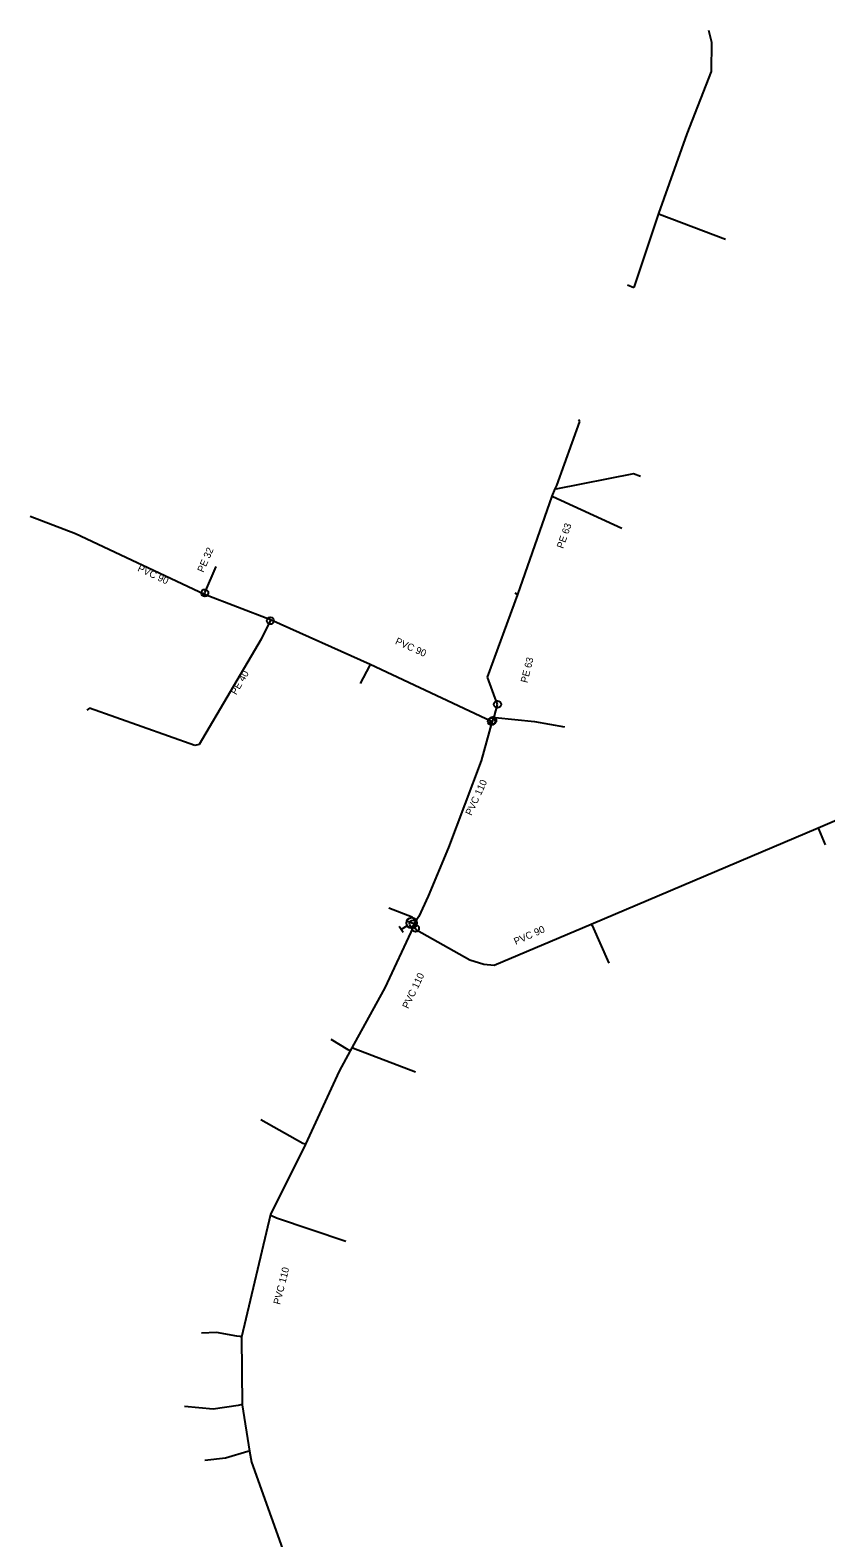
# Model space of a CAD drawing. Extents: x -643485 to -643037, y -1068047 to -1067198.
# Drawn here: x -643329.3 to -643217.2, y -1067410.2 to -1067197.6 of the extents above; entities that cross this region are included whole.
import ezdxf

# ---------------------------------------------------------------- set-up
doc = ezdxf.new("R2010")
doc.units = 0
doc.layers.add('Level 0', color=7, linetype='Continuous')

msp = doc.modelspace()

# ---------------------------------------------------------------- linework, layer by layer
at = {"layer": 'Level 0'}
for p, q in [((-643233.74, -1067197.63), (-643233.31, -1067199.3)), ((-643233.31, -1067199.3), (-643233.34, -1067203.45)), ((-643233.34, -1067203.45), (-643236.81, -1067212.25)), ((-643236.81, -1067212.25), (-643240.79, -1067223.49)), ((-643240.79, -1067223.49), (-643244.28, -1067233.92)), ((-643240.65, -1067223.57), (-643231.34, -1067227.08)), ((-643245.15, -1067233.51), (-643244.28, -1067233.92)), ((-643251.85, -1067252.78), (-643252.07, -1067252.56)), ((-643255.12, -1067261.84), (-643251.85, -1067252.78)), ((-643244.29, -1067260.18), (-643255.25, -1067262.32)), ((-643243.34, -1067260.55), (-643244.29, -1067260.18)), ((-643255.76, -1067263.34), (-643255.35, -1067262.31)), ((-643255.35, -1067262.31), (-643255.12, -1067261.84)), ((-643255.25, -1067262.32), (-643255.35, -1067262.31)), ((-643260.59, -1067277.17), (-643255.76, -1067263.34)), ((-643255.76, -1067263.34), (-643255.66, -1067263.39)), ((-643255.66, -1067263.39), (-643245.97, -1067267.85)), ((-643322.94, -1067268.63), (-643329.34, -1067266.18)), ((-643304.79, -1067277.2), (-643322.94, -1067268.63)), ((-643304.73, -1067276.96), (-643303.11, -1067273.26)), ((-643304.79, -1067277.2), (-643304.73, -1067276.96)), ((-643295.45, -1067280.75), (-643304.79, -1067277.2)), ((-643264.88, -1067288.84), (-643260.59, -1067277.17)), ((-643260.73, -1067277.12), (-643260.99, -1067276.99)), ((-643260.59, -1067277.17), (-643260.73, -1067277.12)), ((-643295.49, -1067280.89), (-643296.8, -1067283.47)), ((-643295.45, -1067280.75), (-643295.49, -1067280.89)), ((-643281.43, -1067287.06), (-643295.45, -1067280.75)), ((-643296.8, -1067283.47), (-643305.54, -1067298.34)), ((-643281.52, -1067287.23), (-643282.82, -1067289.73)), ((-643281.43, -1067287.06), (-643281.52, -1067287.23)), ((-643264.32, -1067295.09), (-643281.43, -1067287.06)), ((-643263.47, -1067292.67), (-643264.88, -1067288.84)), ((-643263.93, -1067294.5), (-643263.47, -1067292.67)), ((-643320.98, -1067293.2), (-643321.37, -1067293.51)), ((-643306.13, -1067298.46), (-643320.98, -1067293.2)), ((-643264.25, -1067295.18), (-643264.32, -1067295.09)), ((-643264.25, -1067295.18), (-643264.14, -1067294.95)), ((-643264.14, -1067294.95), (-643263.93, -1067294.5)), ((-643263.93, -1067294.5), (-643263.82, -1067294.52)), ((-643263.82, -1067294.52), (-643258.25, -1067295.08)), ((-643258.25, -1067295.08), (-643254.02, -1067295.83)), ((-643264.25, -1067295.18), (-643265.76, -1067300.62)), ((-643305.54, -1067298.34), (-643306.13, -1067298.46)), ((-643218.3, -1067310.06), (-643190.8, -1067298.31)), ((-643265.76, -1067300.62), (-643270.36, -1067312.87)), ((-643250.26, -1067323.67), (-643218.3, -1067310.06)), ((-643218.3, -1067310.06), (-643218.24, -1067310.21)), ((-643218.24, -1067310.21), (-643217.29, -1067312.47)), ((-643270.36, -1067312.87), (-643273.25, -1067319.73)), ((-643273.25, -1067319.73), (-643274.57, -1067322.6)), ((-643275.49, -1067322.69), (-643278.78, -1067321.41)), ((-643275.14, -1067322.97), (-643275.49, -1067322.69)), ((-643274.57, -1067322.6), (-643274.94, -1067323.12)), ((-643275.37, -1067324.08), (-643279.37, -1067332.65)), ((-643276.78, -1067324.85), (-643277.32, -1067324)), ((-643276.2, -1067323.89), (-643277.05, -1067324.43)), ((-643274.87, -1067323.74), (-643276.28, -1067323.24)), ((-643275.38, -1067323.58), (-643275.57, -1067323.49)), ((-643275.27, -1067323.67), (-643275.38, -1067323.58)), ((-643275.27, -1067323.67), (-643275.37, -1067324.08)), ((-643275.37, -1067324.08), (-643275.04, -1067324.25)), ((-643274.94, -1067323.12), (-643275.27, -1067323.67)), ((-643274.94, -1067323.12), (-643275.14, -1067322.97)), ((-643275.04, -1067324.25), (-643274.87, -1067324.46)), ((-643274.87, -1067324.46), (-643267.36, -1067328.69)), ((-643263.95, -1067329.44), (-643250.26, -1067323.67)), ((-643250.26, -1067323.67), (-643250.13, -1067323.84)), ((-643250.13, -1067323.84), (-643247.77, -1067329.14)), ((-643267.36, -1067328.69), (-643265.4, -1067329.32)), ((-643265.4, -1067329.32), (-643263.95, -1067329.44)), ((-643279.37, -1067332.65), (-643284.26, -1067341.51)), ((-643284.5, -1067341.36), (-643286.92, -1067339.93)), ((-643284.26, -1067341.51), (-643285.77, -1067344.36)), ((-643284.26, -1067341.51), (-643284.5, -1067341.36)), ((-643284.02, -1067341.07), (-643283.78, -1067341.16)), ((-643283.78, -1067341.16), (-643275.02, -1067344.46)), ((-643285.77, -1067344.36), (-643290.51, -1067354.66)), ((-643290.9, -1067354.6), (-643296.81, -1067351.24)), ((-643290.51, -1067354.66), (-643290.9, -1067354.6)), ((-643290.51, -1067354.66), (-643295.46, -1067364.58)), ((-643295.46, -1067364.58), (-643299.57, -1067381.89)), ((-643295.46, -1067364.58), (-643295.32, -1067364.72)), ((-643295.32, -1067364.72), (-643294.63, -1067365.08)), ((-643294.63, -1067365.08), (-643284.86, -1067368.37)), ((-643303.1, -1067381.21), (-643305.17, -1067381.3)), ((-643300.22, -1067381.74), (-643303.1, -1067381.21)), ((-643299.71, -1067381.78), (-643300.22, -1067381.74)), ((-643299.57, -1067381.89), (-643299.71, -1067381.78)), ((-643299.57, -1067381.89), (-643299.44, -1067391.43)), ((-643303.55, -1067392.05), (-643307.58, -1067391.64)), ((-643300.04, -1067391.52), (-643303.55, -1067392.05)), ((-643299.66, -1067391.41), (-643300.04, -1067391.52)), ((-643299.44, -1067391.43), (-643299.66, -1067391.41)), ((-643299.44, -1067391.43), (-643298.42, -1067397.97)), ((-643301.81, -1067398.94), (-643304.73, -1067399.26)), ((-643298.67, -1067398.01), (-643301.81, -1067398.94)), ((-643298.42, -1067397.97), (-643298.67, -1067398.01)), ((-643298.42, -1067397.97), (-643298.16, -1067399.49)), ((-643298.16, -1067399.49), (-643292.02, -1067416.61))]:
    msp.add_line(p, q, dxfattribs=at)
for centre, radius in [((-643304.73, -1067276.96), 0.5), ((-643295.49, -1067280.89), 0.5), ((-643263.47, -1067292.67), 0.5), ((-643264.32, -1067295.09), 0.5), ((-643264.14, -1067294.95), 0.5), ((-643275.57, -1067323.49), 0.75), ((-643275.38, -1067323.58), 0.5), ((-643275.04, -1067324.25), 0.5)]:
    msp.add_circle(centre, radius, dxfattribs=at)

# ---------------------------------------------------------------- texts
for s, rotation, p in [('PE 63', 70.749, (-643254.22, -1067270.79)), ('PE 32', 66.354, (-643304.92, -1067274.16)), ('PVC 90', 334.724, (-643314.29, -1067273.82)), ('PVC 90', 335.769, (-643277.98, -1067284.12)), ('PE 63', 75.89, (-643259.27, -1067289.72)), ('PE 40', 59.555, (-643300.31, -1067291.41)), ('PVC 110', 65.301, (-643267.14, -1067308.43)), ('PVC 90', 24.058, (-643260.9, -1067326.61)), ('PVC 110', 64.562, (-643276.05, -1067335.66)), ('PVC 110', 75.83, (-643294.12, -1067377.35))]:
    msp.add_text(s, height=1, rotation=rotation, dxfattribs=at).set_placement(p)

doc.saveas('drawing.dxf')
